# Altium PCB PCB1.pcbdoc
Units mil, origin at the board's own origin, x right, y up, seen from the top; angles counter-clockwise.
Board outline 2365 x 1715 mil, 2 copper layers (Top Layer, Bottom Layer), stack 62.206 mil thick; 34 components, 20 nets, 90 pads, 25 vias.
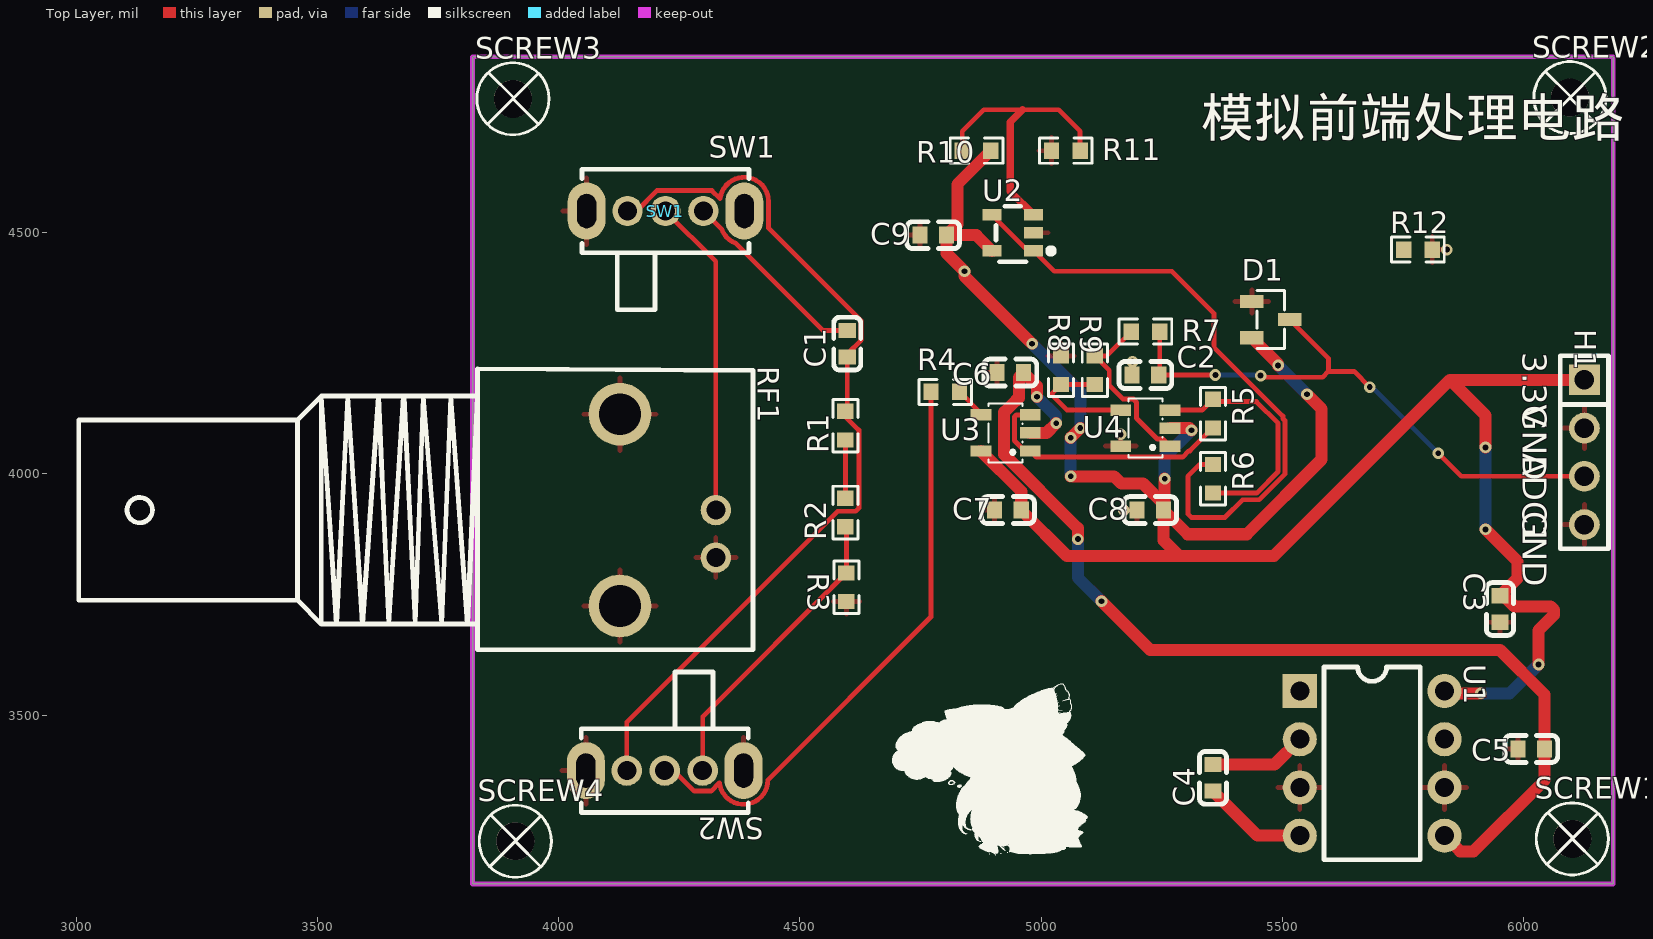
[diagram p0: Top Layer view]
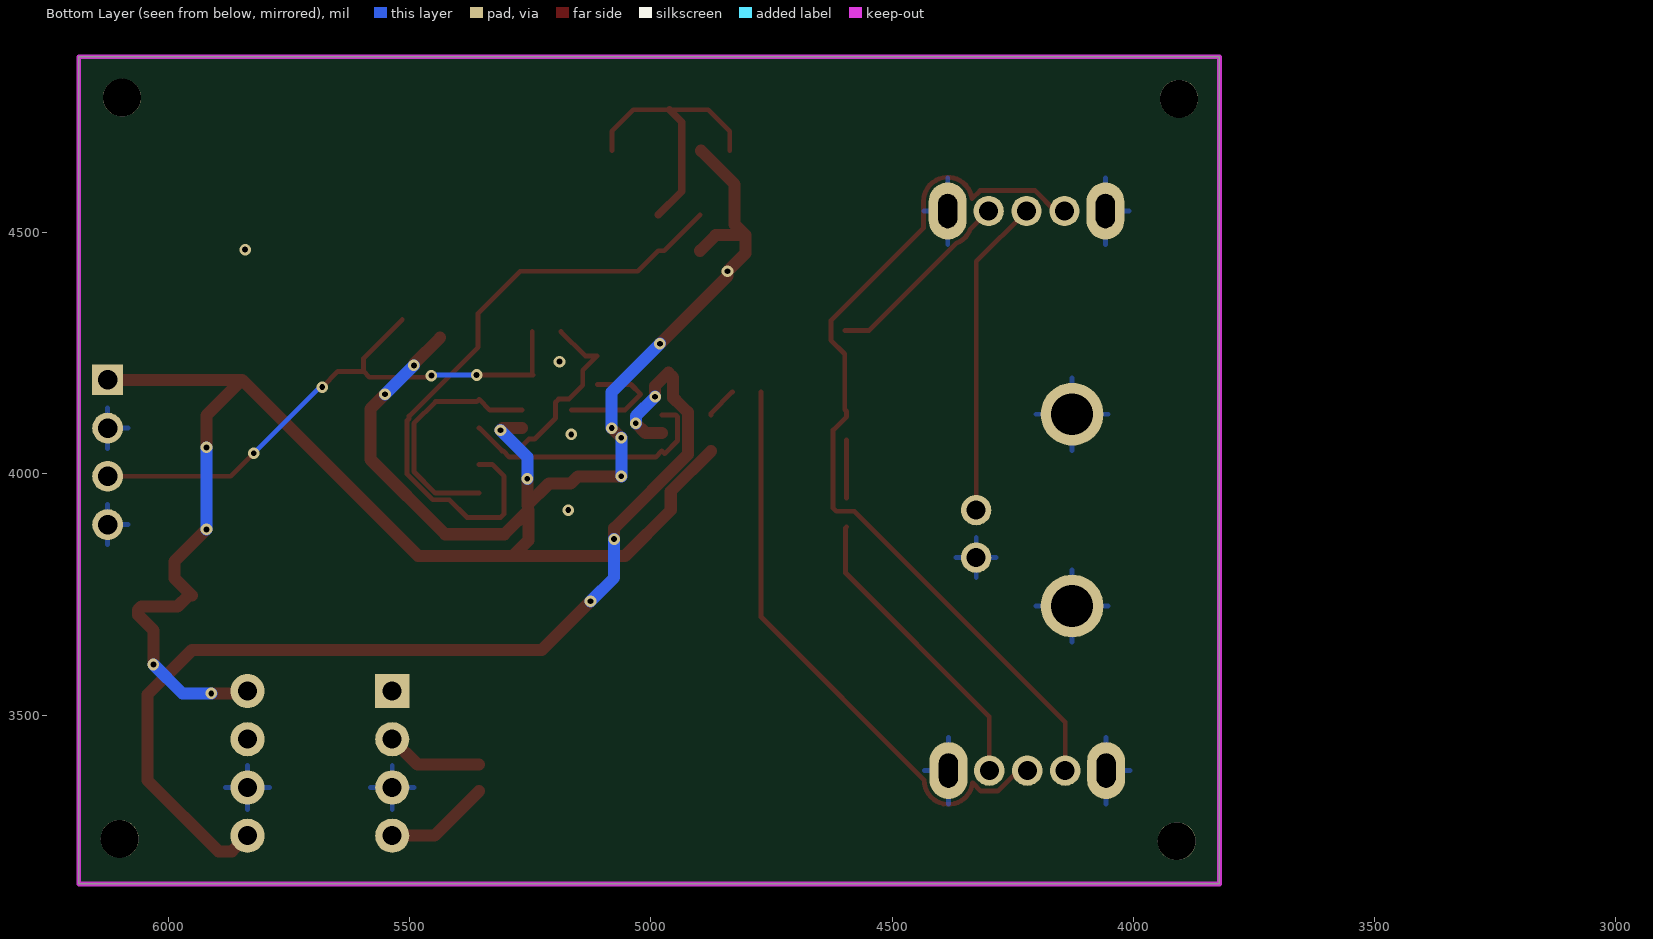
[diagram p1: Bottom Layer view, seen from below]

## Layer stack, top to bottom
Top Solder Mask Layer: solder mask 0.394, Dk 3.3
Top Layer: signal copper 1.379
Dielectric1: surface 59.449, FR4, Dk 4.5
Bottom Layer: signal copper 1.378
Bottom Solder Mask Layer: solder mask 0.394, Dk 3.3

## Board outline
3821.1,4865 6186.1,4865 6186.1,3150 3821.1,3150

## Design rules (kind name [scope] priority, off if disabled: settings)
BoardOutlineClearance copperThickness1oz [All] p0: genericclearance=10 ignorepadtopadclearanceinfootprint=FALSE except(0: Arc-SplitContinuation Track-SplitContinuation SMDPad-SplitContinuation THPad-SplitContinuation Via-SplitContinuation Fill-SplitContinuation Poly-SplitContinuation Region-SplitContinuation Text-SplitContinuation)
BoardOutlineClearance copperThickness2oz [All] p0: genericclearance=10 ignorepadtopadclearanceinfootprint=FALSE except(0: Arc-SplitContinuation Track-SplitContinuation SMDPad-SplitContinuation THPad-SplitContinuation Via-SplitContinuation Fill-SplitContinuation Poly-SplitContinuation Region-SplitContinuation Text-SplitContinuation)
BoardOutlineClearance otherClearance [All] p0: genericclearance=10 ignorepadtopadclearanceinfootprint=FALSE except(0: Arc-SplitContinuation Track-SplitContinuation SMDPad-SplitContinuation THPad-SplitContinuation Via-SplitContinuation Fill-SplitContinuation Poly-SplitContinuation Region-SplitContinuation Text-SplitContinuation)
Clearance copperThickness1oz [All] p1: gap=7 ignorepadtopadclearanceinfootprint=FALSE
Clearance copperThickness2oz [All] p1: gap=7 ignorepadtopadclearanceinfootprint=FALSE
Clearance otherClearance [All] p1: gap=7 ignorepadtopadclearanceinfootprint=FALSE
DiffPairsRouting differentialPair [All] p1: maxuncoupledlength=10 minlimit=6 maxlimit=Infinity mostfreqgap=6 toplayer_minwidth=5 toplayer_prefwidth=10 toplayer_maxwidth=100 bottomlayer_minwidth=5 bottomlayer_prefwidth=10 bottomlayer_maxwidth=100
PasteMaskExpansion pasteMaskExpansion [All] p1: expansion=0
PlaneConnect innerPlane [All] p1: planeconnectstyle=Relief reliefexpansion=20 reliefentries=4 reliefconductorwidth=10 reliefairgap=10
PolygonConnect copperRegion [All] p1: connectstyle=Relief reliefentries=4 reliefconductorwidth=10 polygonreliefangle="90 Angle" airgapwidth=10
RoutingVias viaSize [All] p1: viastyle="Through Hole" holewidth=12.0078 minholewidth=11.811 maxholewidth=248.0314 width=12.0078 minwidth=11.811 maxwidth=248.0314
SolderMaskExpansion solderMaskExpansion [All] p1: useseparateexpansions=TRUE expansion=2 expansionbottom=2
Width copperThickness1oz [All] p1: maxlimit=100 minlimit=5 preferedwidth=10
Width copperThickness2oz [All] p1: maxlimit=100 minlimit=8 preferedwidth=10

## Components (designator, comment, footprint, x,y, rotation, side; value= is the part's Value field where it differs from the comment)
C1 "" C0603 4597.99,4270 r270 top
C2 "" C0603 5216.1,4205 r0 top
C3 "" C0603 5951.1,3720 r270 top
C4 "" C0603 5356.1,3370 r90 top
C5 "" C0603 6016.1,3430 r0 top
C6 "" C0603 4936.1,4210 r0 top
C7 "" C0603 4931.1,3925 r0 top
C8 "" C0603 5226.1,3925 r0 top
C9 "" C0603 4776.1,4495 r0 top
D1 "" SOT-23-3_L2.9-W1.3-P1.90-LS2.4-BR 5476.1,4320 r180 top
H1 "" HDR-TH_4P-HX-PH254-01-04-Z-L11.5 6126.1,4045 r270 top
R1 "" R0603 4594.04,4100 r90 top
R2 "" R0603 4594.04,3920 r90 top
R3 "" R0603 4596.1,3765 r90 top
R4 "" R0603 4801.1,4170 r0 top
R5 "" R0603 5356.1,4125 r90 top
R6 "" R0603 5356.1,3990 r270 top
R7 "" R0603 5216.1,4295 r0 top
R8 "" R0603 5041.1,4215 r270 top
R9 "" R0603 5111.1,4215 r90 top
R10 "" R0603 4866.1,4670 r0 top
R11 "" R0603 5051.1,4670 r0 top
R12 "" R0603 5781.1,4465 r0 top
RF1 "" ANT-TH_KH-BNC75-3511 4226.1,3925 r270 top
SCREW1 "" M2螺丝 6101.1,3243.51 r0 top
SCREW2 "" M2螺丝 6096.1,4780 r0 top
SCREW3 "" M2螺丝 3904.84,4777.72 r0 top
SCREW4 "" M2螺丝 3909.84,3238.51 r0 top
SW1 "" 拨动开关_侧 4221.1,4545 r0 top
SW2 "" 拨动开关_侧 4219.6,3385 r180 top
U1 "" DIP-8_L9.7-W6.4-P2.54-LS7.6-BL 5686.1,3400 r270 top
U2 "" SOT-23-5_L2.9-W1.6-P0.95-LS2.8-BR 4941.1,4500 r0 top
U3 "" SOT-23-5_L3.0-W1.7-P0.95-LS2.8-BR 4926.1,4085 r0 top
U4 "" SOT-23-5_L3.0-W1.7-P0.95-LS2.8-BR 5216.1,4095 r0 top

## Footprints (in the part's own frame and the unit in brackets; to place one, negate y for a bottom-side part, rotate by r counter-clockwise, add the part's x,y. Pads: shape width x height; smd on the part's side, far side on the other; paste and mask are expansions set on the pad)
ANT-TH_KH-BNC75-3511 [mm]
  round 1.6 hole 1: 1(0,2.525) 2(2.5,2.525)
  round 3.3 hole 2.2: 3(5.05,-2.525) 4(-5.05,-2.525)
  silkscreen extent -7.44,-31.02 7.35,4.47
C0603 [mm]
  rect 0.8x0.9 smd: 1(-0.7,0) 2(0.7,0)
  silkscreen extent -1.39,-0.71 1.39,0.71
DIP-8_L9.7-W6.4-P2.54-LS7.6-BL [mm]
  rect 1.8x1.8 hole 1: 1(-3.81,-3.81)
  round 1.8 hole 1: 2(-1.27,-3.81) 3(1.27,-3.81) 4(3.81,-3.81) 5(3.81,3.81) 6(1.27,3.81) 7(-1.27,3.81) 8(-3.81,3.81)
  silkscreen extent -5.08,-2.53 5.08,2.53
HDR-TH_4P-HX-PH254-01-04-Z-L11.5 [mm]
  rect 1.62x1.62 hole 1.02: 1(-3.81,0)
  round 1.62 hole 1.02: 2(-1.27,0) 3(1.27,0) 4(3.81,0)
  silkscreen extent -5.08,-1.27 5.08,1.27
M2螺丝 [mm]
  round 2 hole 2: 1(0,0)
  silkscreen extent -1.9,-1.9 1.9,1.9
R0603 [mil]
  rect 31.75x34.02 smd: 1(-29.66,0) 2(29.66,0)
  silkscreen extent -55,-26 55,26
SOT-23-3_L2.9-W1.3-P1.90-LS2.4-BR [mm]
  rect 1.25x0.7 smd: 1(1,-0.95) 2(1,0.95) 3(-1,0)
  silkscreen extent -0.73,-1.53 0.73,1.53
SOT-23-5_L2.9-W1.6-P0.95-LS2.8-BR [mm]
  rect 1x0.6 smd: 1(1.1,-0.95) 2(1.1,0) 3(1.1,0.95) 4(-1.1,0.95) 5(-1.1,-0.95)
  silkscreen extent -0.89,-1.52 2.16,1.4
SOT-23-5_L3.0-W1.7-P0.95-LS2.8-BR [mm]
  rect 1.1x0.6 smd: 1(1.3,-0.95) 2(1.3,0) 3(1.3,0.95) 4(-1.3,0.95) 5(-1.3,-0.95)
  silkscreen extent -0.9,-1.55 0.9,1.55
拨动开关_侧 [mil]
  round 63 hole 39.4: 1(-78.7,0) 2(0,0) 3(78.7,0)
  oval 78.7x118.1 hole 39.4 slot 70.9 at 90 deg: 4(163.4,0) 5(-163.4,0)
  silkscreen extent -173,-205 173,87

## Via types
v1: diameter 24.02, hole 12.01, Top Layer to Bottom Layer, 25 vias

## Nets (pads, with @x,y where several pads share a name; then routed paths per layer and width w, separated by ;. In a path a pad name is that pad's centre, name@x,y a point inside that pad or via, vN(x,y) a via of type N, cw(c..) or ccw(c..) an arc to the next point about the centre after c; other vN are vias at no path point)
$1N2: RF1.1 SW1.2 | length 663.2
  Top Layer w10: SW1.2 4325.51,4440.59 RF1.1
$1N4: C1.1 SW1.3 | length 401.9
  Top Layer w10: SW1.3 4337.49,4507.31 ccw(c4384.5,4525.3) 4366.51,4478.29 4547.24,4297.56 C1.1
$1N5: C1.2 R1.2 SW1.1 SW2.3 | length 1874.7
  Top Layer w10: SW2.3 4140.9,3485.62 4578.08,3922.8 4615.6,3922.8 4622.03,3929.23 4622.03,4090.77 4594.04,4118.76 R1.2 4597.99,4133.61 C1.2 4597.99,4248.56 4626.69,4277.26 4626.69,4317.86 4434.84,4509.71 4434.84,4564.7 ccw(c4384.5,4564.7) 4334.49,4570.39 4317.4,4587.48 4203.5,4587.48 4161.02,4545 SW1.1
$1N6: R1.1 R2.2 | length 120.7
  Top Layer w10: R2.2 R1.1
$1N7: R2.1 R3.2 SW2.1 | length 629.5
  Top Layer w10: SW2.1 4298.3,3496.86 R3.2 4596.1,3888.28 R2.1
$1N13: R4.1 SW2.2 | length 1235.2
  Top Layer w10: SW2.2 4238.22,3385 4280.7,3342.52 4315.9,3342.52 4332.99,3359.61 ccw(c4383,3365.3) 4433.34,3365.3 4771.44,3703.41 R4.1
$1N23: R5.2 R6.2 U4.3 | length 507.1
  Top Layer w10: U4.3 5333.84,4132.4 R5.2 5360.76,4150 5446.1,4150 5491.1,4105 5491.1,4005 5446.44,3960.34 R6.2
$1N25: R5.1 U3.1 U3.3 | length 539.5
  Top Layer w10: U3.3 4948.5,4122.4 4944.65,4118.55 4944.65,4068.64 4971.49,4041.8 U3.1 4990.08,4034.8 5293.49,4034.8 5306.28,4047.6 5308.36,4047.6 R5.1
$1N26: R8.2 R9.1 U4.4 | length 255.9
  Top Layer w10: R9.1 R8.2 5021.1,4165.34 5021.1,4165 5053.7,4132.4 U4.4
$1N27: R7.1 R9.2 U4.1 | length 367.3
  Top Layer w10: R7.1 5136.1,4244.66 R9.2 5141.1,4214.66 5141.1,4183.78 5169.69,4155.2 5191.12,4155.2 5197.55,4148.76 5197.55,4115.73 5241.08,4072.2 5252.68,4072.2 U4.1
$1N38: C4.2 U1.2 | length 201.7
  Top Layer w25: C4.2 5483.66,3397.56 U1.2
$1N39: C4.1 U1.4 | length 218.3
  Top Layer w25: C4.1 5448.54,3250 U1.4
$1N52: R10.1 R11.2 U2.3 | length 610.1
  Top Layer w10: R10.1 4836.44,4710.34 4881.1,4755 4961.39,4755 5036.1,4755 5080.76,4710.34 R11.2
  Top Layer w15: 4961.39,4755 4936.1,4729.71 4936.1,4585.7 U2.3
$1N56: R6.1 U2.1 U2.4 | length 1320.9
  Top Layer w10: U2.4 4972.59,4462.6 U2.1 5027.01,4420 5271.1,4420 5358.17,4332.93 5358.17,4262.93 5501.1,4120 5501.1,4114.82 5505.12,4110.81 5505.12,3999.19 5452.25,3946.32 5417.43,3946.32 5381.1,3910 5311.1,3910 5304.03,3917.07 5304.03,3995 5328.69,4019.66 R6.1
$1N59: R4.2 U3.4 | length 65.9
  Top Layer w10: R4.2 4874.92,4125.85 U3.4
+3.3V: C3.1 C7.2 C8.2 C9.2 D1.2 H1.1 R10.2 U1.8 U2.5 U3.5 U4.2 | length 4729.7
  Top Layer w25: U3.5 4958.66,3963.86 C7.2 5053.66,3830 5286.1,3830 ; R10.2 4826.1,4600.34 4826.1,4517.44 C9.2 ; U2.5 4865.38,4495 C9.2 ; v1(4981.1,4270) 4841.1,4410 v1(4841.1,4420) 4803.66,4457.44 C9.2 ; v1(5061.1,3995) 5151.1,3995 5166.1,3980 5211.1,3980 5256.1,3935 v1(5256.1,3990) ; v1(5061.1,4075) v1(5081.1,4095) ; U4.2 5307.09,4095 v1(5311.6,4090.5) ; D1.2 5491.1,4228.23 v1(5491.1,4225) ; v1(5551.1,4165) 5581.1,4135 5581.1,4030 5426.1,3875 5303.66,3875 C8.2 5253.66,3862.44 5286.1,3830 ; U1.8 5841.1,3545 v1(5911.1,3545) ; v1(5921.1,3885) 5987.3,3818.8 5987.3,3783.76 C3.1 5958.54,3747.56 5981.1,3725 6056.1,3725 6063.17,3717.93 6063.17,3707.93 6031.1,3675.86 v1(6031.1,3605) ; v1(5921.1,4055) 5921.1,4121.32 5847.42,4195 ; H1.1 5847.42,4195 ; 5286.1,3830 5482.42,3830 5847.42,4195
  Bottom Layer w25: v1(4981.1,4270) 5081.1,4170 v1(5081.1,4095) ; v1(5061.1,3995) v1(5061.1,4075) ; v1(5256.1,3990) 5256.1,4035 v1(5311.6,4090.5) ; v1(5491.1,4225) v1(5551.1,4165) ; v1(5911.1,3545) 5971.1,3545 v1(6031.1,3605) ; v1(5921.1,3885) v1(5921.1,4055)
-3.3V: C5.2 C6.2 U1.5 U3.2 | length 2228.1
  Top Layer w25: U3.2 5011.1,4085 v1(5031.1,4105) ; v1(4991.1,4160) 4991.1,4182.56 C6.2 4953.66,4200 4953.66,4157.77 4948.58,4152.7 4947.98,4152.7 4923.13,4127.85 4923.13,4040.42 5076.1,3887.45 v1(5076.1,3865) ; v1(5125.11,3736) 5226.1,3635 5951.1,3635 6043.66,3542.44 C5.2 6043.66,3365 5896.16,3217.5 5868.6,3217.5 U1.5
  Bottom Layer w25: v1(4991.1,4160) 5031.1,4120 v1(5031.1,4105) ; v1(5076.1,3865) 5076.1,3785 v1(5125.11,3736)
ADC1: C2.2 D1.3 H1.3 R7.2 | length 1211
  Top Layer w10: R7.2 5245.76,4207.1 C2.2 v1(5361.1,4205) ; v1(5454.86,4203.76) 5458.2,4200.42 5583.47,4200.42 5595.55,4212.5 ; D1.3 5595.55,4239.92 5595.55,4212.5 ; v1(5681.1,4180) 5648.6,4212.5 5595.55,4212.5 ; v1(5823.27,4042.84) 5871.1,3995 H1.3
  Bottom Layer w10: v1(5361.1,4205) 5453.62,4205 v1(5454.86,4203.76) ; v1(5681.1,4180) 5686.1,4180 v1(5823.27,4042.84)
AGND: C2.1 C6.1 C7.1 C8.1 C9.1 D1.1 R3.1 R8.1 R11.1 R12.1 RF1.2 RF1.3 RF1.4 SW1.4 SW1.5 SW2.4 SW2.5 U2.2 U4.5
  other v1: 5171.1,3925 5164.92,4081.94 5189.32,4232.96
GND: C3.2 C5.1 H1.2 H1.4 R12.2 U1.3 U1.6
  other v1: 5841.1,4465
pads on no net: SCREW1.1 SCREW2.1 SCREW3.1 SCREW4.1 U1.1 U1.7

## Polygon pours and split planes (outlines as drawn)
AGND on Bottom Layer (solid, remove dead copper, pour order 6): 3566.1,3050 3566.1,5010 5791.1,5010 5781.1,5000 5781.1,3995 5211.1,3425 5211.1,3017.79 5198.31,3005 3611.1,3005
AGND on Top Layer (solid, remove dead copper, pour order 0): 3568.94,5005.88 3564.81,5010 3571.1,5010 3571.1,5005.88
AGND on Top Layer (solid, remove dead copper, pour order 2): 3571.1,3045 3571.1,5005.88 5795.23,5005.88 5781.1,4991.75 5781.1,3990 5776.1,3990 5211.1,3425 5211.1,3015 5209.47,3013.37 3602.73,3013.37
GND on Bottom Layer (solid, remove dead copper, pour order 10): 6391.1,3000 5225.8,3000 5211.1,3014.69 5211.1,3415 5781.1,3985 5781.1,5000 5811.1,5030 6391.1,5030
GND on Top Layer (solid, remove dead copper, pour order 4): 6391.1,3000 5211.1,3000 5206.1,3005 5206.1,3415.52 5780.58,3990 5781.1,3990 5781.1,5015 5786.1,5020 6376.1,5020 6391.1,5035

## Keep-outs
Board Outline Layer:
  the board outline again, w10

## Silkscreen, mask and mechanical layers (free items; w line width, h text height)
Top Silkscreen Layer:
  drawing of 159 lines, arcs and shapes, not listed
  text "模拟前端处理电路" at 5331.1,4700 h80
  text "SW1" at 4311.1,4655 h45
  text "3.3V" at 5998.6,4252.5 h50 r270
  text "GND" at 5998.6,4142.5 h50 r270
  text "ADC1" at 5998.6,4042.5 h50 r270
  text "GND" at 5998.6,3922.5 h50 r270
